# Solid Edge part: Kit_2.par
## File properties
Sűrűség: 0,000 kg/m^3
Pontosság: 0,990
Author: bmolnar
Last saved by: bmolnar
Revision: 77
Username: bmolnar
Dokumentum tartalom típus: 0
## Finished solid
Body 1: solid body, 23 faces, 39 edges, 29 vertices.
  Faces by surface: cylinder 10, plane 9, cone 3, torus 1
  Edges by curve: circle 25, line 14
Bounding box of the edges (mm; curved faces can reach further): 35.700 x 35.525 x 3.850, from (-17.85, -16.85, 0.6) to (17.85, 18.675, 4.45).
Cylindrical faces by radius (mm): R1.25 x2, R2.5 x4, R11.5 x1, R15.375 x1, R16.85 x1, R17.85 x1
Conical faces (half-angle, radius in mm at the cone's reference point): 45 deg R11.25 x1, 45 deg R16.75 x2
Toroidal faces (ring radius, tube radius in mm): R11.9 r0.4 x1
Planar faces by outward normal: +z 2, -z 5, oblique 2
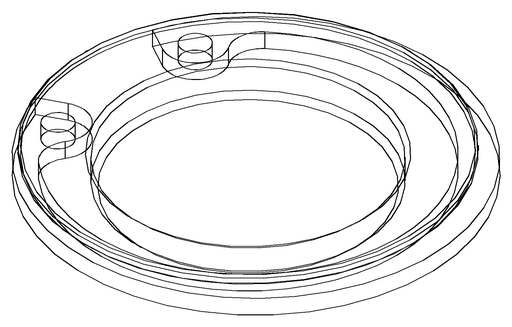
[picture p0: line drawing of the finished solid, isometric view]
